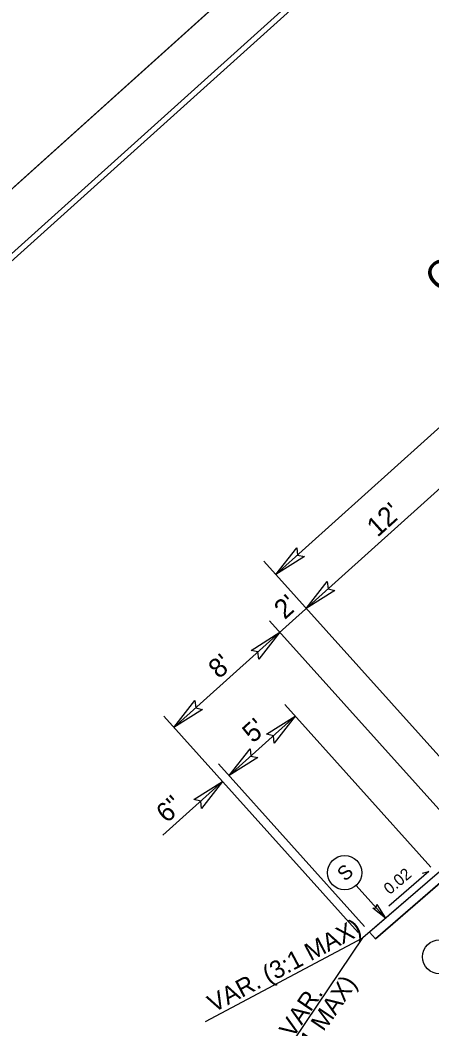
# Model space of a CAD drawing. Extents: x 2488411 to 2488707, y 383669 to 383962.
# Drawn here: x 2488541.5 to 2488564.6, y 383844.8 to 383900.8 of the extents above; entities that cross this region are included whole.
import ezdxf

# ---------------------------------------------------------------- set-up
doc = ezdxf.new("R2010")
doc.units = 0
for name, color, linetype in [('Old_Level_19', 7, 'Continuous'), ('Old_Level_21', 7, 'Continuous'), ('Old_Level_44', 7, 'Continuous'), ('Prop DSN Text', 7, 'Continuous'), ('Prop Paint Stripe', 7, 'Continuous'), ('Prop PFL Text', 7, 'Continuous'), ('Prop Roadway Profile Bench Mark Info Text', 7, 'Continuous'), ('Prop Vertical Profile Curve Label', 7, 'Continuous'), ('Prop XS SE Text', 7, 'Continuous'), ('Sheet Cutting Line CELL', 7, 'Continuous'), ('Sheet Profile Grid Major CELL', 7, 'Continuous'), ('Sheet Sticker Preliminary CELL', 7, 'Continuous'), ('Sheet Title CELL', 7, 'Continuous'), ('Typical Hinge Slope Arterial CELL', 7, 'Continuous'), ('Typical Text General CELL', 7, 'Continuous')]:
    doc.layers.add(name, color=color, linetype=linetype)

msp = doc.modelspace()

# ---------------------------------------------------------------- linework, layer by layer
at = {"layer": 'Old_Level_19'}
msp.add_lwpolyline([(2488619.231, 383961.604), (2488468.948, 383826.508), (2488557.194, 383728.341), (2488707.477, 383863.438)], close=True, dxfattribs=at)
at = {"layer": 'Old_Level_21'}
msp.add_lwpolyline([(2488620.631, 383959.24), (2488471.909, 383825.547), (2488556.553, 383731.388), (2488705.275, 383865.081)], close=True, dxfattribs=at)
at = {"layer": 'Prop DSN Text'}
msp.add_line((2488560.41, 383852.215), (2488562.071, 383850.367), dxfattribs=at)
for centre in [(2488559.767, 383852.93), (2488565.11, 383848.203)]:
    msp.add_circle(centre, 0.962, dxfattribs=at)
at = {"layer": 'Prop Paint Stripe'}
msp.add_lwpolyline([(2488561.585, 383851.14), (2488562.071, 383850.367), (2488561.347, 383850.933), (2488561.543, 383850.954)], close=True, dxfattribs=at)
at = {"layer": 'Prop PFL Text'}
for p, q in [((2488564.509, 383852.994), (2488562.261, 383851.055)), ((2488564.154, 383852.897), (2488564.509, 383852.994))]:
    msp.add_line(p, q, dxfattribs=at)
at = {"layer": 'Prop Vertical Profile Curve Label'}
msp.add_line((2488566.477, 383854.164), (2488560.797, 383849.268), dxfattribs=at)
at = {"layer": 'Prop XS SE Text'}
msp.add_line((2488619.231, 383961.604), (2488468.948, 383826.508), dxfattribs=at)
at = {"layer": 'Sheet Cutting Line CELL'}
msp.add_lwpolyline([(2488619.72, 383958.009), (2488485.857, 383837.674), (2488570.092, 383743.97), (2488703.955, 383864.305)], close=True, dxfattribs=at)
at = {"layer": 'Sheet Profile Grid Major CELL'}
for p, q in [((2488564.962, 383852.858), (2488561.173, 383849.593)), ((2488565.296, 383852.486), (2488561.508, 383849.221)), ((2488561.508, 383849.221), (2488565.275, 383852.468)), ((2488561.173, 383849.593), (2488561.508, 383849.221)), ((2488561.173, 383849.593), (2488561.508, 383849.221))]:
    msp.add_line(p, q, dxfattribs=at)
at = {"layer": 'Sheet Sticker Preliminary CELL'}
for points in [[(2488557.509, 383870.683), (2488555.899, 383869.669), (2488557.078, 383871.178), (2488557.123, 383870.77)], [(2488559.22, 383868.779), (2488557.61, 383867.766), (2488558.789, 383869.274), (2488558.834, 383868.866)], [(2488554.513, 383865.416), (2488556.123, 383866.429), (2488554.944, 383864.921), (2488554.899, 383865.329)], [(2488551.786, 383862.096), (2488550.176, 383861.083), (2488551.355, 383862.591), (2488551.4, 383862.183)], [(2488555.385, 383860.707), (2488556.995, 383861.72), (2488555.816, 383860.212), (2488555.771, 383860.62)], [(2488554.886, 383859.391), (2488553.276, 383858.378), (2488554.455, 383859.886), (2488554.5, 383859.478)], [(2488551.297, 383857.032), (2488552.907, 383858.045), (2488551.727, 383856.537), (2488551.683, 383856.945)]]:
    msp.add_lwpolyline(points, close=True, dxfattribs=at)
at = {"layer": 'Sheet Title CELL'}
for p, q in [((2488550.176, 383861.083), (2488591.806, 383898.506)), ((2488555.899, 383869.669), (2488582.661, 383893.727)), ((2488568.264, 383855.915), (2488555.219, 383870.426)), ((2488566.613, 383854.761), (2488555.55, 383867.066)), ((2488564.612, 383853.247), (2488556.401, 383862.38)), ((2488560.524, 383849.572), (2488549.603, 383861.72)), ((2488553.276, 383858.378), (2488556.995, 383861.72)), ((2488560.894, 383849.904), (2488552.683, 383859.038)), ((2488549.558, 383855.035), (2488552.907, 383858.045))]:
    msp.add_line(p, q, dxfattribs=at)
at = {"layer": 'Typical Text General CELL'}
for p in [(2488551.942, 383844.576), (2488555.33, 383841.167)]:
    msp.add_line(p, (2488560.797, 383849.268), dxfattribs=at)

# ---------------------------------------------------------------- texts
at = {"layer": 'Old_Level_44'}
msp.add_text('S', height=0.8, rotation=41.9538, dxfattribs=at).set_placement((2488559.795, 383852.406))
at = {"layer": 'Prop PFL Text'}
msp.add_text('0.02 ', height=0.6476, rotation=40.1454, dxfattribs=at).set_placement((2488562.299, 383851.665))
at = {"layer": 'Prop Roadway Profile Bench Mark Info Text'}
for s, rotation, p in [('VAR. (3:1 MAX)', 27.9176, (2488552.405, 383845.056)), ('(3:1 MAX)', 55.9901, (2488557.129, 383841.727)), ('VAR.', 55.9901, (2488556.857, 383843.591))]:
    msp.add_text(s, height=1, rotation=rotation, dxfattribs=at).set_placement(p)
at = {"layer": 'Sheet Title CELL'}
for s, p in [("12'", (2488561.618, 383871.734)), ("2'", (2488556.405, 383867.112)), ("8'", (2488552.71, 383863.777)), ("5'", (2488554.621, 383860.165)), ('6"', (2488549.776, 383855.673))]:
    msp.add_text(s, height=1.0817, rotation=41.9538, dxfattribs=at).set_placement(p)
at = {"layer": 'Typical Hinge Slope Arterial CELL'}
msp.add_text('C', height=1.64, rotation=41.9538, dxfattribs=at).set_placement((2488565.192, 383885.354))

doc.saveas('drawing.dxf')
